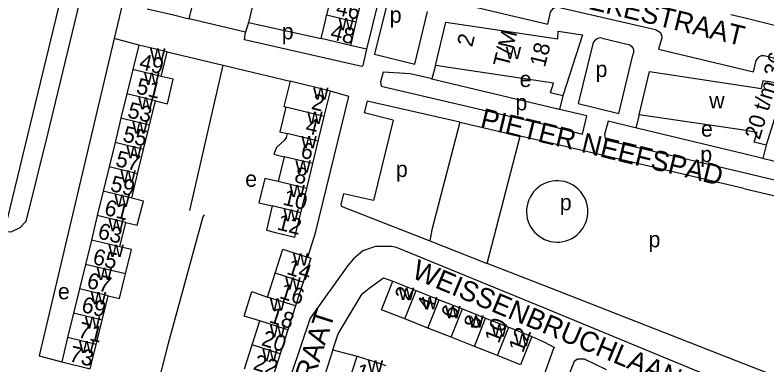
# Model space of a CAD drawing. Extents: x 162804 to 165059, y 381530 to 382901.
# Drawn here: x 163167.6 to 163355.8, y 382106.1 to 382193.6 of the extents above; entities that cross this region are included whole.
import ezdxf

# ---------------------------------------------------------------- set-up
doc = ezdxf.new("R2010")
doc.units = 0
for name, color, linetype in [('BLT_Basislijn', 7, 'Continuous'), ('BLT_Bebouwing', 7, 'Continuous'), ('BLT_Centroide', 7, 'Continuous'), ('BLT_Huisnummer', 7, 'Continuous'), ('BLT_Huisnummer_ tussenligend', 7, 'Continuous'), ('BLT_Huisnummer_reeks', 7, 'Continuous'), ('BLT_Onderverdeling_panden', 7, 'Continuous'), ('BLT_Straatnaam', 7, 'Continuous')]:
    doc.layers.add(name, color=color, linetype=linetype)

msp = doc.modelspace()

# ---------------------------------------------------------------- linework, layer by layer
at = {"layer": 'BLT_Basislijn'}
for p, q in [((163165.71, 382142.61), (163180.08, 382202)), ((163225.3, 382189.39), (163211.18, 382192.74)), ((163350, 382192.91), (163346.74, 382193.7)), ((163358.4, 382190.86), (163350, 382192.91)), ((163226.04, 382191.82), (163225.3, 382189.39)), ((163226.04, 382191.82), (163244.22, 382187.78)), ((163198.56, 382186.14), (163192.45, 382187.78)), ((163314.53, 382187.9), (163320.85, 382186.39)), ((163255.59, 382185.1), (163251.54, 382186.05)), ((163205.71, 382184.41), (163219.7, 382181.07)), ((163211.36, 382144.75), (163219.7, 382181.07)), ((163219.7, 382181.07), (163236.43, 382177.08)), ((163272.81, 382181.05), (163271.94, 382177.68)), ((163271.64, 382177.75), (163271.94, 382177.68)), ((163271.94, 382177.68), (163303.46, 382170.15)), ((163304.72, 382173.41), (163303.86, 382170.05)), ((163303.86, 382170.05), (163303.46, 382170.15)), ((163262.24, 382167.36), (163255, 382169.16)), ((163323.82, 382168.72), (163322.97, 382165.42)), ((163262.24, 382167.36), (163257.31, 382147.26)), ((163278.9, 382166.83), (163294.06, 382163.33)), ((163323.54, 382165.29), (163322.97, 382165.42)), ((163350, 382158.92), (163323.54, 382165.29)), ((163285.79, 382131.52), (163294.06, 382163.33)), ((163355.66, 382161.1), (163354.79, 382157.76)), ((163354.79, 382157.76), (163350, 382158.92)), ((163355.35, 382157.63), (163354.79, 382157.76)), ((163257.31, 382147.26), (163249.83, 382148.94)), ((163271.43, 382137.15), (163285.79, 382131.52)), ((163247.12, 382109.91), (163253.22, 382108.33))]:
    msp.add_line(p, q, dxfattribs=at)
for points in [[(163192.95, 382234.99), (163175.84, 382164.21), (163170.27, 382141.99), (163168.83, 382140.38), (163166.54, 382139.37), (163162.62, 382139.53), (163094.62, 382155.39), (163082.92, 382158.66), (163072.72, 382162.36)], [(163232.31, 382218.4), (163232.15, 382217.01), (163226.04, 382191.82)], [(163261.67, 382209.71), (163260.2, 382203.78), (163255.59, 382185.1)], [(163261.67, 382209.71), (163265.61, 382208.78), (163266.28, 382207.25), (163266.85, 382206.42), (163268.55, 382204.6), (163269.58, 382203.94), (163271.08, 382203.3), (163275.86, 382202.37), (163277.16, 382201.84), (163277.74, 382201.31), (163278.09, 382200.55), (163278.05, 382199.93), (163277.17, 382196.99), (163301, 382191.35), (163301.64, 382194.39), (163302.29, 382195.27), (163303.24, 382195.67), (163327.96, 382190), (163329.15, 382189.3), (163329.43, 382188.52), (163329.51, 382187.93), (163328.68, 382185.09), (163350, 382180.01)], [(163194.61, 382196.83), (163194.54, 382196.53), (163192.45, 382187.78)], [(163260.73, 382196.61), (163257.55, 382183.86), (163267.65, 382181.38), (163270.84, 382194.52)], [(163255.59, 382185.1), (163255.52, 382184.81), (163254.65, 382181), (163254.42, 382180.81), (163225.03, 382187.41), (163225.3, 382189.39)], [(163192.45, 382187.78), (163173.65, 382108.41), (163179.29, 382106.88)], [(163314.53, 382187.9), (163314.11, 382187.91), (163313.7, 382187.83), (163313.31, 382187.68), (163312.95, 382187.46), (163312.65, 382187.18), (163312.4, 382186.84), (163312.2, 382186.41)], [(163312.2, 382186.41), (163308.57, 382171.51), (163318.73, 382169.01), (163322.33, 382183.98)], [(163320.85, 382186.39), (163321.22, 382186.3), (163321.57, 382186.13), (163321.87, 382185.89), (163322.11, 382185.6), (163322.29, 382185.26), (163322.4, 382184.89), (163322.43, 382184.51), (163322.37, 382184.13), (163322.33, 382183.98)], [(163350, 382180.01), (163352.49, 382179.42), (163353.13, 382182.25), (163353.42, 382182.71), (163353.83, 382183.19), (163354.42, 382183.5), (163355.08, 382183.55), (163379.43, 382177.52), (163380.27, 382176.67), (163380.47, 382175.72), (163379.74, 382172.38), (163402.79, 382166.81), (163403.83, 382170.46), (163404.78, 382171.08), (163405.34, 382171.07), (163420.21, 382167.4), (163421.32, 382167.32), (163424.15, 382168.12), (163426.19, 382169.4), (163427.59, 382171.76), (163430.47, 382171.07)], [(163271.64, 382177.75), (163266.51, 382178.96), (163259.79, 382179.35), (163259.12, 382176.91), (163259.25, 382175.84), (163300, 382166.31), (163309.68, 382163.82), (163310.75, 382168.41), (163303.86, 382170.05)], [(163240.92, 382133.05), (163242.77, 382139.14), (163251.14, 382173.3), (163246.54, 382174.62)], [(163278.9, 382166.83), (163255.76, 382172.11), (163255, 382169.16)], [(163278.9, 382166.83), (163271.96, 382139.91), (163271.43, 382137.15)], [(163322.97, 382165.42), (163322.46, 382165.55), (163316.03, 382167.07), (163315.17, 382163.77), (163315.39, 382162.43), (163350, 382154.22)], [(163350, 382150.26), (163300, 382162.02), (163294.06, 382163.33)], [(163350, 382154.22), (163361.86, 382151.41), (163362.7, 382155.86), (163355.35, 382157.63)], [(163311, 382144.51), (163310.96, 382145.29), (163310.84, 382146.07), (163310.64, 382146.83), (163310.37, 382147.56), (163310.02, 382148.26), (163309.6, 382148.93), (163309.12, 382149.54), (163308.58, 382150.11), (163307.98, 382150.62), (163307.33, 382151.06), (163306.64, 382151.43), (163305.92, 382151.74), (163305.17, 382151.97), (163304.4, 382152.12), (163303.62, 382152.19), (163302.84, 382152.18), (163302.06, 382152.09), (163301.29, 382151.92), (163300.55, 382151.68), (163299.83, 382151.36), (163299.15, 382150.97), (163298.52, 382150.51), (163297.93, 382149.99), (163297.4, 382149.41), (163296.93, 382148.79), (163296.53, 382148.11), (163296.2, 382147.4), (163295.94, 382146.66), (163295.76, 382145.9), (163295.66, 382145.12), (163295.64, 382144.34), (163295.69, 382143.56), (163295.83, 382142.79), (163296.04, 382142.03), (163296.33, 382141.3), (163296.7, 382140.61), (163297.13, 382139.96), (163297.62, 382139.35), (163298.18, 382138.8), (163298.79, 382138.3), (163299.45, 382137.88), (163300.14, 382137.52), (163300.87, 382137.23), (163301.62, 382137.02), (163302.4, 382136.88), (163303.18, 382136.83), (163303.96, 382136.86), (163304.74, 382136.96), (163305.5, 382137.15), (163306.24, 382137.41), (163306.95, 382137.74), (163307.62, 382138.15), (163308.24, 382138.62), (163308.82, 382139.15), (163309.34, 382139.74), (163309.79, 382140.38), (163310.18, 382141.06), (163310.49, 382141.78), (163310.74, 382142.52), (163310.9, 382143.29), (163310.98, 382144.07), (163311, 382144.51)], [(163350, 382150.26), (163427.51, 382132.02), (163427.76, 382131.26), (163417.05, 382080.47), (163416.15, 382080.25), (163412.43, 382081.95), (163350, 382106.4)], [(163249.83, 382148.94), (163249.16, 382146.32), (163249.27, 382145.83), (163271.43, 382137.15)], [(163214.96, 382143.64), (163214.64, 382143.13), (163205.97, 382111.5), (163202.88, 382099.5)], [(163350, 382099.73), (163300, 382120.36), (163263.12, 382135.5), (163261.91, 382135.74), (163257.79, 382135.78), (163254.65, 382134.65), (163252.36, 382132.68), (163250.88, 382131.03), (163241.51, 382117.79), (163231.95, 382089.64), (163228.22, 382090.96)], [(163350, 382106.4), (163300, 382125.98), (163285.79, 382131.52)], [(163247.12, 382109.91), (163248.47, 382113.89), (163254.53, 382123.88), (163256.22, 382125.33), (163259.84, 382127.93), (163262.18, 382127.03)], [(163296.97, 382113.25), (163300, 382111.89), (163302.63, 382110.48), (163302.37, 382110.21), (163300, 382103.44), (163272.16, 382035.29), (163272.03, 382034.98)], [(163247.12, 382109.91), (163228.44, 382051.49), (163228.33, 382051.13)], [(163315.65, 382104.85), (163310.14, 382107.53), (163308.4, 382107.58), (163307.55, 382107), (163300.8, 382089.94)]]:
    msp.add_lwpolyline(points, dxfattribs=at)
at = {"layer": 'BLT_Bebouwing'}
for p, q in [((163246.98, 382199.4), (163245.6, 382193.59)), ((163254.29, 382197.67), (163252.91, 382191.86)), ((163252.91, 382191.86), (163251.54, 382186.05)), ((163272.81, 382181.05), (163275.43, 382191.86)), ((163251.54, 382186.05), (163244.22, 382187.78)), ((163198.56, 382186.14), (163197.08, 382180.05)), ((163205.71, 382184.41), (163198.56, 382186.14)), ((163204.22, 382178.31), (163205.71, 382184.41)), ((163197.08, 382180.05), (163195.6, 382173.95)), ((163246.54, 382174.62), (163236.43, 382177.08)), ((163195.6, 382173.95), (163194.12, 382167.85)), ((163244.99, 382168.28), (163246.54, 382174.62)), ((163201.26, 382166.12), (163202.74, 382172.22)), ((163235.37, 382170.62), (163233.87, 382164.44)), ((163243.49, 382162.1), (163244.99, 382168.28)), ((163350, 382164.81), (163323.82, 382168.72)), ((163194.12, 382167.85), (163192.64, 382161.76)), ((163199.78, 382160.02), (163201.26, 382166.12)), ((163233.87, 382164.44), (163235.73, 382163.99)), ((163192.64, 382161.76), (163191.15, 382155.66)), ((163242.12, 382156.47), (163243.49, 382162.1)), ((163198.29, 382153.92), (163199.78, 382160.02)), ((163234.98, 382158.21), (163233.47, 382152.01)), ((163191.15, 382155.66), (163189.67, 382149.56)), ((163240.61, 382150.27), (163242.12, 382156.47)), ((163196.81, 382147.83), (163198.29, 382153.92)), ((163189.67, 382149.56), (163188.19, 382143.47)), ((163239.13, 382144.18), (163240.61, 382150.27)), ((163188.19, 382143.47), (163186.71, 382137.37)), ((163193.85, 382135.63), (163195.33, 382141.73)), ((163186.71, 382137.37), (163185.22, 382131.27)), ((163185.22, 382131.27), (163183.74, 382125.18)), ((163230.77, 382123.11), (163232.69, 382129.1)), ((163239.71, 382126.85), (163237.79, 382120.87)), ((163262.18, 382127.03), (163267.98, 382124.74)), ((163183.74, 382125.18), (163182.26, 382119.08)), ((163189.4, 382117.34), (163190.88, 382123.44)), ((163267.98, 382124.74), (163273.78, 382122.44)), ((163273.78, 382122.44), (163279.58, 382120.14)), ((163237.79, 382120.87), (163235.88, 382114.89)), ((163279.58, 382120.14), (163285.37, 382117.85)), ((163182.26, 382119.08), (163180.77, 382112.98)), ((163270.97, 382115.35), (163265.17, 382117.64)), ((163285.37, 382117.85), (163291.17, 382115.55)), ((163187.92, 382111.24), (163189.4, 382117.34)), ((163226.95, 382111.15), (163228.86, 382117.13)), ((163291.17, 382115.55), (163296.97, 382113.25)), ((163235.88, 382114.89), (163233.96, 382108.91)), ((163276.77, 382113.05), (163270.97, 382115.35)), ((163180.77, 382112.98), (163179.29, 382106.88)), ((163282.57, 382110.76), (163276.77, 382113.05)), ((163186.43, 382105.15), (163187.92, 382111.24)), ((163225.03, 382105.17), (163226.95, 382111.15)), ((163288.36, 382108.46), (163282.57, 382110.76)), ((163233.96, 382108.91), (163232.05, 382102.93)), ((163251.32, 382102.42), (163253.22, 382108.33)), ((163179.29, 382106.88), (163186.43, 382105.15))]:
    msp.add_line(p, q, dxfattribs=at)
for points in [[(163211.18, 382192.74), (163212.76, 382199.2), (163209.5, 382199.95)], [(163200.68, 382195.23), (163207.27, 382193.67), (163211.18, 382192.74)], [(163244.22, 382187.78), (163245.37, 382192.65), (163245.6, 382193.59)], [(163275.43, 382191.86), (163303.46, 382187.66), (163303.56, 382189.62), (163309.63, 382188.72), (163304.72, 382173.41)], [(163304.72, 382173.41), (163301.65, 382174.2), (163302.37, 382176.62), (163272.81, 382181.05)], [(163202.74, 382172.22), (163205.76, 382171.46), (163207.22, 382177.59), (163204.22, 382178.31)], [(163323.82, 382168.72), (163326.42, 382179.49), (163350, 382175.97)], [(163236.43, 382177.08), (163234.88, 382170.74), (163235.37, 382170.62)], [(163350, 382175.97), (163354.44, 382175.3), (163354.86, 382177.27), (163360.39, 382176.39), (163355.66, 382161.1)], [(163355.66, 382161.1), (163352.62, 382161.84), (163353.36, 382164.3), (163350, 382164.81)], [(163235.73, 382163.99), (163235.49, 382163.01), (163235.01, 382162.29), (163233.05, 382160.55), (163232.34, 382158.85), (163234.98, 382158.21)], [(163233.47, 382152.01), (163230.14, 382152.79), (163228.66, 382146.7), (163231.99, 382145.92)], [(163195.33, 382141.73), (163198.21, 382141.09), (163199.72, 382147.11), (163196.81, 382147.83)], [(163231.99, 382145.92), (163230.51, 382139.83), (163232.79, 382139.28), (163237.65, 382138.1), (163239.13, 382144.18)], [(163195.23, 382128.87), (163196.73, 382134.98), (163193.85, 382135.63)], [(163232.69, 382129.1), (163234.6, 382135.07), (163236.86, 382134.35), (163240.92, 382133.05)], [(163240.92, 382133.05), (163241.62, 382132.83), (163239.71, 382126.85)], [(163190.88, 382123.44), (163193.75, 382122.77), (163195.23, 382128.87)], [(163265.17, 382117.64), (163259.37, 382119.94), (163262.18, 382127.03)], [(163228.86, 382117.13), (163224.93, 382118.34), (163226.9, 382124.5), (163230.77, 382123.11)], [(163296.97, 382113.25), (163294.16, 382106.16), (163288.36, 382108.46)], [(163253.22, 382108.33), (163257.98, 382106.8), (163260.42, 382106.01)]]:
    msp.add_lwpolyline(points, dxfattribs=at)
at = {"layer": 'BLT_Onderverdeling_panden'}
for p, q in [((163252.91, 382191.86), (163245.6, 382193.59)), ((163204.22, 382178.31), (163197.08, 382180.05)), ((163202.74, 382172.22), (163195.6, 382173.95)), ((163244.99, 382168.28), (163235.37, 382170.62)), ((163201.26, 382166.12), (163194.12, 382167.85)), ((163243.49, 382162.1), (163235.73, 382163.99)), ((163199.78, 382160.02), (163192.64, 382161.76)), ((163242.12, 382156.47), (163234.98, 382158.21)), ((163198.29, 382153.92), (163191.15, 382155.66)), ((163240.61, 382150.27), (163233.47, 382152.01)), ((163196.81, 382147.83), (163189.67, 382149.56)), ((163239.13, 382144.18), (163231.99, 382145.92)), ((163195.33, 382141.73), (163188.19, 382143.47)), ((163193.85, 382135.63), (163186.71, 382137.37)), ((163195.23, 382128.87), (163185.22, 382131.27)), ((163239.71, 382126.85), (163232.69, 382129.1)), ((163190.88, 382123.44), (163183.74, 382125.18)), ((163237.79, 382120.87), (163230.77, 382123.11)), ((163265.17, 382117.64), (163267.98, 382124.74)), ((163270.97, 382115.35), (163273.78, 382122.44)), ((163276.77, 382113.05), (163279.58, 382120.14)), ((163189.4, 382117.34), (163182.26, 382119.08)), ((163282.57, 382110.76), (163285.37, 382117.85)), ((163235.88, 382114.89), (163228.86, 382117.13)), ((163288.36, 382108.46), (163291.17, 382115.55)), ((163187.92, 382111.24), (163180.77, 382112.98)), ((163233.96, 382108.91), (163226.95, 382111.15))]:
    msp.add_line(p, q, dxfattribs=at)

# ---------------------------------------------------------------- texts
at = {"layer": 'BLT_Centroide'}
for s, p in [('p', (163261.39, 382191.72)), ('w', (163248.57, 382189.81)), ('p', (163234.37, 382187.56)), ('w', (163201.39, 382182.22)), ('w', (163290.44, 382182.62)), ('p', (163312.91, 382178.14)), ('w', (163199.91, 382176.12)), ('e', (163293.9, 382175.64)), ('w', (163242.23, 382172.44)), ('w', (163198.42, 382170.03)), ('p', (163292.86, 382169.8)), ('w', (163341.35, 382170.31)), ('w', (163240.75, 382166.38)), ('w', (163196.95, 382163.94)), ('e', (163339.3, 382163.23)), ('w', (163239.27, 382160.28)), ('w', (163195.47, 382157.84)), ('p', (163339.13, 382156.84)), ('w', (163237.78, 382154.19)), ('p', (163262.93, 382153.13)), ('w', (163193.98, 382151.75)), ('e', (163225.22, 382150.68)), ('w', (163236.3, 382148.09)), ('w', (163192.5, 382145.66)), ('p', (163303.96, 382144.8)), ('w', (163234.81, 382142)), ('w', (163191.02, 382139.56)), ('p', (163326.17, 382135.54)), ('w', (163190.97, 382133.12)), ('w', (163237.15, 382130.97)), ('w', (163188.05, 382127.34)), ('w', (163235.24, 382124.97)), ('e', (163178.33, 382122.53)), ('w', (163263.67, 382122.34)), ('w', (163186.56, 382121.25)), ('w', (163269.47, 382120.05)), ('w', (163231.39, 382119.69)), ('w', (163275.27, 382117.75)), ('w', (163185.09, 382115.16)), ('w', (163281.06, 382115.45)), ('w', (163231.41, 382113.03)), ('w', (163286.88, 382113.16)), ('w', (163292.66, 382110.86)), ('w', (163183.61, 382109.06)), ('w', (163229.49, 382107.03)), ('w', (163255.88, 382104.22))]:
    msp.add_text(s, height=4, dxfattribs=at).set_placement(p)
at = {"layer": 'BLT_Huisnummer'}
for s, rotation, p in [('48', 346.653, (163246.31, 382187.67)), ('49', 346.3303, (163198.46, 382180.19)), ('2', 346.3213, (163241.57, 382170.19)), ('53', 346.3361, (163195.54, 382168.08)), ('6', 346.3213, (163238.87, 382158.04)), ('57', 346.3342, (163192.55, 382155.92)), ('61', 346.3324, (163189.72, 382143.7)), ('12', 346.3224, (163232.96, 382140.04)), ('65', 346.3305, (163186.83, 382131.42)), ('14', 342.2583, (163235.38, 382128.93)), ('2', 68.3897, (163266.19, 382121.95)), ('69', 346.3305, (163184.01, 382119.42)), ('18', 342.2559, (163230.99, 382116.86)), ('6', 68.3939, (163277.78, 382117.35)), ('12', 68.3967, (163294.7, 382108.97)), ('73', 346.3363, (163180.94, 382107.09)), ('22', 342.261, (163226.97, 382105.08)), ('1', 342.1968, (163252.53, 382102.85))]:
    msp.add_text(s, height=4, rotation=rotation, dxfattribs=at).set_placement(p)
at = {"layer": 'BLT_Huisnummer_ tussenligend'}
for s, rotation, p in [('46', 346.653, (163247.69, 382193.79)), ('51', 346.3303, (163197.71, 382174.1)), ('4', 346.3213, (163240.09, 382164.21)), ('55', 346.3361, (163194.34, 382162.1)), ('8', 346.3213, (163237.29, 382151.92)), ('59', 346.3342, (163191.23, 382149.68)), ('10', 346.3213, (163234.42, 382146.26)), ('63', 346.3324, (163188.09, 382137.83)), ('67', 346.3305, (163185.35, 382125.45)), ('16', 342.2583, (163233.55, 382122.92)), ('4', 68.3897, (163271.69, 382119.43)), ('8', 68.3939, (163283.45, 382114.86)), ('10', 68.3939, (163288.68, 382111.3)), ('71', 346.3305, (163183.13, 382113.07)), ('20', 342.2559, (163229.04, 382111.11))]:
    msp.add_text(s, height=4, rotation=rotation, dxfattribs=at).set_placement(p)
at = {"layer": 'BLT_Huisnummer_reeks'}
for s, rotation, p in [('T/M', 76.0061, (163291.11, 382180.37)), ('2 ', 76.0061, (163282.02, 382185.5)), ('18', 76.0061, (163300.24, 382180.41)), ('20 t/m 36', 73.2389, (163353.98, 382162.26))]:
    msp.add_text(s, height=4, rotation=rotation, dxfattribs=at).set_placement(p)
at = {"layer": 'BLT_Straatnaam'}
for s, height, rotation, p in [('PERMEKESTRAAT', 5, 346.3764, (163292.1, 382199.78)), ('PIETER NEEFSPAD', 5, 346.3764, (163283.8, 382165.55)), ('WEISSENBRUCHLAAN', 5, 337.2526, (163266.63, 382128)), ('CASPAR NETSCHERSTRAAT', 4.9999, 72.2045, (163219.49, 382030.87))]:
    msp.add_text(s, height=height, rotation=rotation, dxfattribs=at).set_placement(p)

doc.saveas('drawing.dxf')
